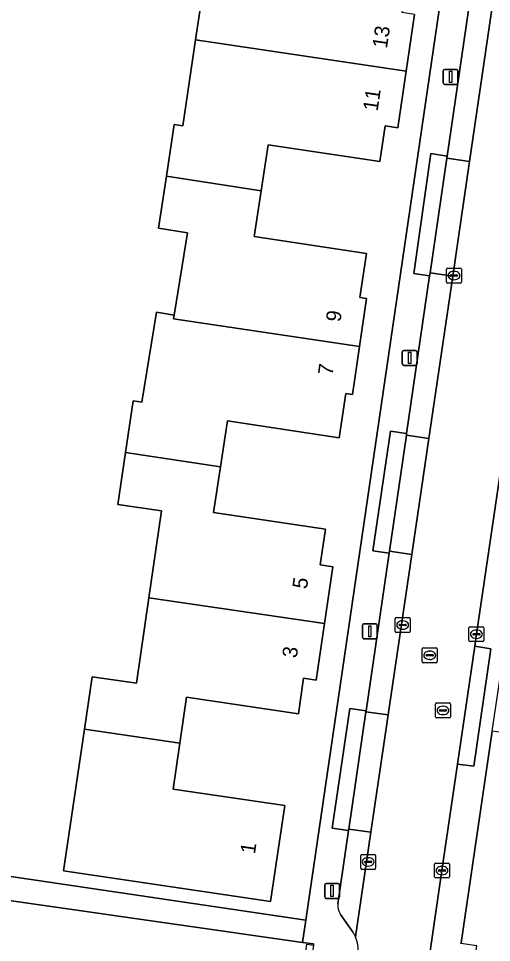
# Model space of a CAD drawing. Extents: x 164148 to 165261, y 382513 to 383432.
# Drawn here: x 164508.4 to 164540.2, y 382867.8 to 382929.8 of the extents above; entities that cross this region are included whole.
import ezdxf

# ---------------------------------------------------------------- set-up
doc = ezdxf.new("R2010")
doc.units = 0
for name, color, linetype in [('IMGEO_Erf', 7, 'Continuous'), ('IMGEO_Greppel_droge_sloot', 7, 'Continuous'), ('IMGEO_Groenvoorziening', 7, 'Continuous'), ('IMGEO_Kolk', 7, 'Continuous'), ('IMGEO_Lichtmast', 7, 'Continuous'), ('IMGEO_Pand', 7, 'Continuous'), ('IMGEO_Pand_nummerreeks', 7, 'Continuous'), ('IMGEO_Parkeervlak_open', 7, 'Continuous'), ('IMGEO_Rijbaan_lokaal_open', 7, 'Continuous'), ('IMGEO_Rioolput', 7, 'Continuous'), ('IMGEO_Voetpad_open', 7, 'Continuous')]:
    doc.layers.add(name, color=color, linetype=linetype)

msp = doc.modelspace()

# ---------------------------------------------------------------- linework, layer by layer
at = {"layer": 'IMGEO_Erf'}
msp.add_lwpolyline([(164536.67, 382930.425), (164544.133, 382980.726), (164542.913, 382982.243), (164519.298, 382985.737), (164495.986, 382989.176), (164494.523, 382988.072), (164478.67, 382881.048), (164478.137, 382876.668), (164527.73, 382869.322)], close=True, dxfattribs=at)
for points in [[(164535.03, 382930.101), (164534.467, 382926.303), (164533.904, 382922.504), (164533.057, 382922.633), (164532.702, 382920.244), (164525.197, 382921.358), (164524.728, 382918.276), (164524.258, 382915.194), (164531.797, 382914.074), (164531.359, 382911.106), (164531.805, 382911.044), (164531.329, 382907.829), (164530.852, 382904.613), (164530.422, 382904.67), (164529.967, 382901.7), (164522.469, 382902.828), (164522.001, 382899.752), (164521.532, 382896.676), (164529.042, 382895.565), (164528.691, 382893.168), (164529.541, 382893.043), (164528.982, 382889.238), (164528.423, 382885.433), (164527.578, 382885.569), (164527.229, 382883.186), (164519.728, 382884.295), (164519.273, 382881.212), (164518.818, 382878.129), (164526.315, 382877.031), (164525.363, 382870.591), (164511.47, 382872.646), (164512.877, 382882.156), (164513.394, 382885.655), (164516.368, 382885.227), (164517.196, 382890.97), (164518.037, 382896.807), (164515.115, 382897.228), (164515.63, 382900.722), (164516.141, 382904.189), (164516.733, 382904.093), (164517.701, 382910.122), (164518.893, 382909.931), (164519.78, 382915.457), (164517.849, 382915.767), (164518.367, 382919.245), (164518.884, 382922.722), (164519.473, 382922.626), (164520.329, 382928.398), (164521.189, 382934.198)], [(164547.639, 382932.325), (164544.836, 382913.278), (164561.257, 382910.871), (164561.444, 382912.157), (164568.951, 382911.025), (164568.121, 382905.277), (164560.589, 382906.422), (164560.768, 382907.691), (164544.373, 382910.128), (164540.7, 382885.173), (164557.112, 382882.794), (164557.31, 382884.103), (164564.82, 382882.958), (164563.954, 382877.188), (164556.429, 382878.318), (164556.635, 382879.621), (164540.236, 382882.018), (164538.147, 382867.82)]]:
    msp.add_lwpolyline(points, dxfattribs=at)
at = {"layer": 'IMGEO_Greppel_droge_sloot'}
msp.add_lwpolyline([(164527.808, 382867.71), (164528.242, 382867.643), (164528.255, 382867.732), (164527.513, 382867.841), (164483.733, 382874.094), (164468.94, 382876.903), (164467.772, 382876.998), (164467.128, 382872.489), (164466.901, 382870.898), (164466.447, 382867.72), (164465.924, 382864.054), (164484.051, 382861.245), (164524.835, 382854.782), (164525.957, 382854.773), (164526.609, 382859.328), (164526.913, 382861.453), (164527.19, 382863.393)], close=True, dxfattribs=at)
at = {"layer": 'IMGEO_Groenvoorziening'}
msp.add_lwpolyline([(164478.137, 382876.668), (164478.67, 382881.048), (164471.849, 382882.015), (164467.712, 382879.403), (164467.374, 382877.067), (164467.772, 382876.998), (164468.94, 382876.903), (164483.733, 382874.094), (164527.513, 382867.841), (164527.73, 382869.322)], close=True, dxfattribs=at)
at = {"layer": 'IMGEO_Kolk'}
for p, q in [((164537.168, 382912.156), (164537.168, 382913.008)), ((164537.243, 382913.082), (164538.095, 382913.082)), ((164538.169, 382913.008), (164538.169, 382912.156)), ((164537.427, 382912.576), (164537.427, 382912.588)), ((164537.865, 382912.539), (164537.467, 382912.539)), ((164537.47, 382912.625), (164537.868, 382912.625)), ((164537.679, 382912.302), (164537.654, 382912.302)), ((164537.656, 382912.862), (164537.681, 382912.862)), ((164537.911, 382912.588), (164537.911, 382912.576)), ((164538.095, 382912.082), (164537.243, 382912.082)), ((164533.729, 382888.709), (164533.729, 382889.561)), ((164533.804, 382889.635), (164534.656, 382889.635)), ((164534.217, 382889.415), (164534.242, 382889.415)), ((164534.73, 382889.561), (164534.73, 382888.709)), ((164533.988, 382889.129), (164533.988, 382889.141)), ((164534.426, 382889.092), (164534.028, 382889.092)), ((164534.031, 382889.178), (164534.429, 382889.178)), ((164534.24, 382888.855), (164534.215, 382888.855)), ((164534.472, 382889.141), (164534.472, 382889.129)), ((164538.68, 382888.093), (164538.68, 382888.945)), ((164538.755, 382889.019), (164539.607, 382889.019)), ((164539.168, 382888.799), (164539.193, 382888.799)), ((164539.681, 382888.945), (164539.681, 382888.093)), ((164534.656, 382888.635), (164533.804, 382888.635)), ((164538.939, 382888.513), (164538.939, 382888.525)), ((164539.377, 382888.476), (164538.979, 382888.476)), ((164538.982, 382888.562), (164539.38, 382888.562)), ((164539.191, 382888.239), (164539.166, 382888.239)), ((164539.423, 382888.525), (164539.423, 382888.513)), ((164539.607, 382888.019), (164538.755, 382888.019)), ((164531.413, 382872.815), (164531.413, 382873.667)), ((164531.488, 382873.741), (164532.34, 382873.741)), ((164531.672, 382873.235), (164531.672, 382873.247)), ((164532.11, 382873.198), (164531.712, 382873.198)), ((164531.715, 382873.284), (164532.113, 382873.284)), ((164531.901, 382873.521), (164531.926, 382873.521)), ((164532.156, 382873.247), (164532.156, 382873.235)), ((164532.414, 382873.667), (164532.414, 382872.815)), ((164532.34, 382872.741), (164531.488, 382872.741)), ((164531.924, 382872.961), (164531.899, 382872.961)), ((164536.367, 382872.237), (164536.367, 382873.089)), ((164536.442, 382873.163), (164537.294, 382873.163)), ((164536.626, 382872.657), (164536.626, 382872.669)), ((164537.064, 382872.62), (164536.666, 382872.62)), ((164536.669, 382872.706), (164537.067, 382872.706)), ((164536.855, 382872.943), (164536.88, 382872.943)), ((164537.11, 382872.669), (164537.11, 382872.657)), ((164537.368, 382873.089), (164537.368, 382872.237)), ((164537.294, 382872.163), (164536.442, 382872.163)), ((164536.878, 382872.383), (164536.853, 382872.383))]:
    msp.add_line(p, q, dxfattribs=at)
for points in [[(164537.168, 382912.156), (164537.168, 382913.008)], [(164537.243, 382913.082), (164538.095, 382913.082)], [(164538.169, 382913.008), (164538.169, 382912.156)], [(164538.095, 382912.082), (164537.243, 382912.082)], [(164533.729, 382888.709), (164533.729, 382889.561)], [(164533.804, 382889.635), (164534.656, 382889.635)], [(164534.73, 382889.561), (164534.73, 382888.709)], [(164538.68, 382888.093), (164538.68, 382888.945)], [(164538.755, 382889.019), (164539.607, 382889.019)], [(164539.681, 382888.945), (164539.681, 382888.093)], [(164534.656, 382888.635), (164533.804, 382888.635)], [(164539.607, 382888.019), (164538.755, 382888.019)], [(164531.413, 382872.815), (164531.413, 382873.667)], [(164531.488, 382873.741), (164532.34, 382873.741)], [(164532.414, 382873.667), (164532.414, 382872.815)], [(164532.34, 382872.741), (164531.488, 382872.741)], [(164536.367, 382872.237), (164536.367, 382873.089)], [(164536.442, 382873.163), (164537.294, 382873.163)], [(164537.368, 382873.089), (164537.368, 382872.237)], [(164537.294, 382872.163), (164536.442, 382872.163)]]:
    msp.add_lwpolyline(points, dxfattribs=at)
for centre, radius, start, end in [((164537.245, 382913.006), 0.0765, 91.55205, 178.44795), ((164537.245, 382913.006), 0.0765, 91.55205, 178.44795), ((164538.093, 382913.006), 0.0765, 1.55205, 88.44795), ((164538.093, 382913.006), 0.0765, 1.55205, 88.44795), ((164537.467, 382912.585), 0.0403, 85.87752, 175.75265), ((164537.464, 382912.575), 0.0366, 178.93798, 274.71019), ((164537.868, 382912.582), 0.043, 264.86636, 352.45326), ((164537.872, 382912.587), 0.0386, 1.73085, 96.63898), ((164537.245, 382912.158), 0.0765, 181.55205, 268.44795), ((164537.245, 382912.158), 0.0765, 181.55205, 268.44795), ((164538.093, 382912.158), 0.0765, 271.55205, 358.44795), ((164538.093, 382912.158), 0.0765, 271.55205, 358.44795), ((164533.806, 382889.559), 0.0765, 91.55205, 178.44795), ((164533.806, 382889.559), 0.0765, 91.55205, 178.44795), ((164534.654, 382889.559), 0.0765, 1.55205, 88.44795), ((164534.654, 382889.559), 0.0765, 1.55205, 88.44795), ((164533.806, 382888.711), 0.0765, 181.55205, 268.44795), ((164533.806, 382888.711), 0.0765, 181.55205, 268.44795), ((164534.028, 382889.138), 0.0403, 85.87752, 175.75265), ((164534.025, 382889.128), 0.0366, 178.93798, 274.71019), ((164534.429, 382889.135), 0.043, 264.86636, 352.45326), ((164534.433, 382889.14), 0.0386, 1.73085, 96.63898), ((164534.654, 382888.711), 0.0765, 271.55205, 358.44795), ((164534.654, 382888.711), 0.0765, 271.55205, 358.44795), ((164538.757, 382888.943), 0.0765, 91.55205, 178.44795), ((164538.757, 382888.943), 0.0765, 91.55205, 178.44795), ((164539.605, 382888.943), 0.0765, 1.55205, 88.44795), ((164539.605, 382888.943), 0.0765, 1.55205, 88.44795), ((164538.757, 382888.095), 0.0765, 181.55205, 268.44795), ((164538.757, 382888.095), 0.0765, 181.55205, 268.44795), ((164538.979, 382888.522), 0.0403, 85.87752, 175.75265), ((164538.976, 382888.512), 0.0366, 178.93798, 274.71019), ((164539.38, 382888.519), 0.043, 264.86636, 352.45326), ((164539.384, 382888.524), 0.0386, 1.73085, 96.63898), ((164539.605, 382888.095), 0.0765, 271.55205, 358.44795), ((164539.605, 382888.095), 0.0765, 271.55205, 358.44795), ((164531.49, 382873.665), 0.0765, 91.55205, 178.44795), ((164531.49, 382873.665), 0.0765, 91.55205, 178.44795), ((164531.712, 382873.244), 0.0403, 85.87752, 175.75265), ((164531.709, 382873.234), 0.0366, 178.93798, 274.71019), ((164532.113, 382873.241), 0.043, 264.86636, 352.45326), ((164532.117, 382873.246), 0.0386, 1.73085, 96.63898), ((164532.338, 382873.665), 0.0765, 1.55205, 88.44795), ((164532.338, 382873.665), 0.0765, 1.55205, 88.44795), ((164531.49, 382872.817), 0.0765, 181.55205, 268.44795), ((164531.49, 382872.817), 0.0765, 181.55205, 268.44795), ((164532.338, 382872.817), 0.0765, 271.55205, 358.44795), ((164532.338, 382872.817), 0.0765, 271.55205, 358.44795), ((164536.444, 382873.087), 0.0765, 91.55205, 178.44795), ((164536.444, 382873.087), 0.0765, 91.55205, 178.44795), ((164536.666, 382872.666), 0.0403, 85.87752, 175.75265), ((164536.663, 382872.656), 0.0366, 178.93798, 274.71019), ((164537.067, 382872.663), 0.043, 264.86636, 352.45326), ((164537.071, 382872.668), 0.0386, 1.73085, 96.63898), ((164537.292, 382873.087), 0.0765, 1.55205, 88.44795), ((164537.292, 382873.087), 0.0765, 1.55205, 88.44795), ((164536.444, 382872.239), 0.0765, 181.55205, 268.44795), ((164536.444, 382872.239), 0.0765, 181.55205, 268.44795), ((164537.292, 382872.239), 0.0765, 271.55205, 358.44795), ((164537.292, 382872.239), 0.0765, 271.55205, 358.44795)]:
    msp.add_arc(centre, radius, start, end, dxfattribs=at)
for centre, major_axis, ratio, start_param, end_param in [((164537.655, 382912.582), (-0.387, 0.002), 0.722429, 4.712389, 7.853982), ((164537.68, 382912.582), (-0.39, 0.002), 0.717154, 1.570796, 4.712389), ((164534.216, 382889.135), (-0.387, 0.002), 0.722429, 4.712389, 7.853982), ((164534.241, 382889.135), (-0.39, 0.002), 0.717154, 1.570796, 4.712389), ((164539.167, 382888.519), (-0.387, 0.002), 0.722429, 4.712389, 7.853982), ((164539.192, 382888.519), (-0.39, 0.002), 0.717154, 1.570796, 4.712389), ((164531.9, 382873.241), (-0.387, 0.002), 0.722429, 4.712389, 7.853982), ((164531.925, 382873.241), (-0.39, 0.002), 0.717154, 1.570796, 4.712389), ((164536.854, 382872.663), (-0.387, 0.002), 0.722429, 4.712389, 7.853982), ((164536.879, 382872.663), (-0.39, 0.002), 0.717154, 1.570796, 4.712389)]:
    msp.add_ellipse(centre, major_axis=major_axis, ratio=ratio, start_param=start_param, end_param=end_param, dxfattribs=at)
at = {"layer": 'IMGEO_Lichtmast'}
for p, q in [((164536.949, 382925.514), (164536.949, 382926.314)), ((164536.949, 382926.314), (164536.949, 382925.514)), ((164537.049, 382926.414), (164537.839, 382926.414)), ((164537.839, 382926.414), (164537.049, 382926.414)), ((164537.939, 382926.314), (164537.939, 382925.514)), ((164537.939, 382925.514), (164537.939, 382926.314)), ((164537.839, 382925.414), (164537.049, 382925.414)), ((164537.049, 382925.414), (164537.839, 382925.414)), ((164534.204, 382906.658), (164534.204, 382907.458)), ((164534.204, 382907.458), (164534.204, 382906.658)), ((164534.304, 382907.558), (164535.094, 382907.558)), ((164535.094, 382907.558), (164534.304, 382907.558)), ((164535.194, 382907.458), (164535.194, 382906.658)), ((164535.194, 382906.658), (164535.194, 382907.458)), ((164535.094, 382906.558), (164534.304, 382906.558)), ((164534.304, 382906.558), (164535.094, 382906.558)), ((164531.531, 382888.315), (164531.531, 382889.115)), ((164531.531, 382889.115), (164531.531, 382888.315)), ((164531.631, 382889.215), (164532.421, 382889.215)), ((164532.421, 382889.215), (164531.631, 382889.215)), ((164532.521, 382889.115), (164532.521, 382888.315)), ((164532.521, 382888.315), (164532.521, 382889.115)), ((164532.421, 382888.215), (164531.631, 382888.215)), ((164531.631, 382888.215), (164532.421, 382888.215)), ((164528.999, 382870.893), (164528.999, 382871.693)), ((164528.999, 382871.693), (164528.999, 382870.893)), ((164529.099, 382871.793), (164529.889, 382871.793)), ((164529.889, 382871.793), (164529.099, 382871.793)), ((164529.989, 382871.693), (164529.989, 382870.893)), ((164529.989, 382870.893), (164529.989, 382871.693)), ((164529.889, 382870.793), (164529.099, 382870.793)), ((164529.099, 382870.793), (164529.889, 382870.793))]:
    msp.add_line(p, q, dxfattribs=at)
for points in [[(164537.369, 382926.289), (164537.519, 382926.289), (164537.519, 382925.539), (164537.369, 382925.539), (164537.369, 382926.289)], [(164534.624, 382907.433), (164534.774, 382907.433), (164534.774, 382906.683), (164534.624, 382906.683), (164534.624, 382907.433)], [(164531.951, 382889.09), (164532.101, 382889.09), (164532.101, 382888.34), (164531.951, 382888.34), (164531.951, 382889.09)], [(164529.419, 382871.668), (164529.569, 382871.668), (164529.569, 382870.918), (164529.419, 382870.918), (164529.419, 382871.668)]]:
    msp.add_lwpolyline(points, dxfattribs=at)
for centre, start, end in [((164537.049, 382926.314), 90, 180), ((164537.049, 382926.314), 90, 180), ((164537.839, 382926.314), 0, 90), ((164537.839, 382926.314), 360, 90), ((164537.049, 382925.514), 180, 270), ((164537.049, 382925.514), 180, 270), ((164537.839, 382925.514), 270, 0), ((164537.839, 382925.514), 270, 0), ((164534.304, 382907.458), 90, 180), ((164534.304, 382907.458), 90, 180), ((164535.094, 382907.458), 0, 90), ((164535.094, 382907.458), 360, 90), ((164534.304, 382906.658), 180, 270), ((164534.304, 382906.658), 180, 270), ((164535.094, 382906.658), 270, 0), ((164535.094, 382906.658), 270, 0), ((164531.631, 382889.115), 90, 180), ((164531.631, 382889.115), 90, 180), ((164532.421, 382889.115), 0, 90), ((164532.421, 382889.115), 360, 90), ((164531.631, 382888.315), 180, 270), ((164531.631, 382888.315), 180, 270), ((164532.421, 382888.315), 270, 0), ((164532.421, 382888.315), 270, 0), ((164529.099, 382871.693), 90, 180), ((164529.099, 382871.693), 90, 180), ((164529.889, 382871.693), 0, 90), ((164529.889, 382871.693), 360, 90), ((164529.099, 382870.893), 180, 270), ((164529.099, 382870.893), 180, 270), ((164529.889, 382870.893), 270, 0), ((164529.889, 382870.893), 270, 0)]:
    msp.add_arc(centre, 0.1, start, end, dxfattribs=at)
at = {"layer": 'IMGEO_Pand'}
for points in [[(164534.539, 382932.609), (164527.04, 382933.727), (164527.481, 382936.808), (164521.094, 382937.721), (164520.588, 382934.288), (164521.189, 382934.198), (164520.329, 382928.398), (164534.467, 382926.303), (164535.03, 382930.101), (164534.185, 382930.228)], [(164534.467, 382926.303), (164520.329, 382928.398), (164519.473, 382922.626), (164518.884, 382922.722), (164518.367, 382919.245), (164524.728, 382918.276), (164525.197, 382921.358), (164532.702, 382920.244), (164533.057, 382922.633), (164533.904, 382922.504)], [(164531.797, 382914.074), (164524.258, 382915.194), (164524.728, 382918.276), (164518.367, 382919.245), (164517.849, 382915.767), (164519.78, 382915.457), (164518.893, 382909.931), (164518.852, 382909.677), (164531.329, 382907.829), (164531.805, 382911.044), (164531.359, 382911.106)], [(164531.329, 382907.829), (164518.852, 382909.677), (164518.893, 382909.931), (164517.701, 382910.122), (164516.733, 382904.093), (164516.141, 382904.189), (164515.63, 382900.722), (164522.001, 382899.752), (164522.469, 382902.828), (164529.967, 382901.7), (164530.422, 382904.67), (164530.852, 382904.613)], [(164529.042, 382895.565), (164521.532, 382896.676), (164522.001, 382899.752), (164515.63, 382900.722), (164515.115, 382897.228), (164518.037, 382896.807), (164517.196, 382890.97), (164528.982, 382889.238), (164529.541, 382893.043), (164528.691, 382893.168)], [(164528.982, 382889.238), (164517.196, 382890.97), (164516.368, 382885.227), (164513.394, 382885.655), (164512.877, 382882.156), (164519.273, 382881.212), (164519.728, 382884.295), (164527.229, 382883.186), (164527.578, 382885.569), (164528.423, 382885.433)], [(164526.315, 382877.031), (164518.818, 382878.129), (164519.273, 382881.212), (164512.877, 382882.156), (164511.47, 382872.646), (164525.363, 382870.591)]]:
    msp.add_lwpolyline(points, close=True, dxfattribs=at)
at = {"layer": 'IMGEO_Parkeervlak_open'}
for points in [[(164540.312, 382931.053), (164538.776, 382931.269), (164538.763, 382931.18), (164537.216, 382920.605), (164537.196, 382920.467), (164538.721, 382920.241)], [(164537.586, 382912.536), (164536.069, 382912.76), (164536.041, 382912.575), (164534.494, 382901.996), (164534.476, 382901.877), (164535.985, 382901.658)], [(164534.839, 382893.869), (164533.337, 382894.09), (164533.317, 382893.95), (164531.771, 382883.381), (164531.762, 382883.32), (164533.255, 382883.11)]]:
    msp.add_lwpolyline(points, close=True, dxfattribs=at)
for points in [[(164532.094, 382875.226), (164530.609, 382875.44), (164530.594, 382875.339), (164529.877, 382870.437)], [(164531.063, 382868.222), (164532.094, 382875.226)], [(164530.061, 382869.713), (164530.863, 382868.563)]]:
    msp.add_lwpolyline(points, dxfattribs=at)
for centre, radius, start, end in [((164531.014, 382870.341), 1.141, 175.14797, 213.37097), ((164529.289, 382867.411), 1.951, 24.57653, 36.20759)]:
    msp.add_arc(centre, radius, start, end, dxfattribs=at)
at = {"layer": 'IMGEO_Rijbaan_lokaal_open'}
for points in [[(164539.063, 382887.71), (164539.181, 382888.519), (164542.028, 382907.811), (164542.057, 382908.011), (164543.215, 382915.889), (164545.41, 382930.835), (164546.177, 382936.01), (164547.348, 382943.904), (164548.568, 382952.133), (164550.358, 382964.172), (164551.53, 382972.055), (164553.09, 382982.535)], [(164547.198, 382977.836), (164545.744, 382967.958), (164544.187, 382957.375), (164543.057, 382949.701), (164541.441, 382938.72), (164540.312, 382931.053), (164538.721, 382920.241), (164537.586, 382912.536), (164535.985, 382901.658), (164534.839, 382893.869), (164533.255, 382883.11), (164532.094, 382875.226), (164531.063, 382868.222)], [(164534.057, 382852.71), (164536.025, 382866.945), (164536.868, 382872.663), (164537.91, 382879.804), (164539.063, 382887.71)]]:
    msp.add_lwpolyline(points, dxfattribs=at)
msp.add_arc((164529.284, 382867.405), 1.957, 350.53101, 24.67146, dxfattribs=at)
at = {"layer": 'IMGEO_Rioolput'}
for p, q in [((164535.548, 382886.677), (164535.548, 382887.529)), ((164535.623, 382887.603), (164536.475, 382887.603)), ((164536.549, 382887.529), (164536.549, 382886.677)), ((164535.807, 382887.097), (164535.807, 382887.109)), ((164536.245, 382887.06), (164535.847, 382887.06)), ((164535.85, 382887.146), (164536.248, 382887.146)), ((164536.036, 382887.383), (164536.061, 382887.383)), ((164536.291, 382887.109), (164536.291, 382887.097)), ((164536.475, 382886.603), (164535.623, 382886.603)), ((164536.059, 382886.823), (164536.034, 382886.823)), ((164536.435, 382882.979), (164536.435, 382883.831)), ((164536.51, 382883.905), (164537.362, 382883.905)), ((164537.436, 382883.831), (164537.436, 382882.979)), ((164536.694, 382883.399), (164536.694, 382883.411)), ((164537.132, 382883.362), (164536.734, 382883.362)), ((164536.737, 382883.448), (164537.135, 382883.448)), ((164536.946, 382883.125), (164536.921, 382883.125)), ((164536.923, 382883.685), (164536.948, 382883.685)), ((164537.178, 382883.411), (164537.178, 382883.399)), ((164537.362, 382882.905), (164536.51, 382882.905))]:
    msp.add_line(p, q, dxfattribs=at)
for points in [[(164535.548, 382886.677), (164535.548, 382887.529)], [(164535.623, 382887.603), (164536.475, 382887.603)], [(164536.549, 382887.529), (164536.549, 382886.677)], [(164536.475, 382886.603), (164535.623, 382886.603)], [(164536.435, 382882.979), (164536.435, 382883.831)], [(164536.51, 382883.905), (164537.362, 382883.905)], [(164537.436, 382883.831), (164537.436, 382882.979)], [(164537.362, 382882.905), (164536.51, 382882.905)]]:
    msp.add_lwpolyline(points, dxfattribs=at)
for centre, radius, start, end in [((164535.625, 382887.527), 0.0765, 91.55205, 178.44795), ((164535.625, 382887.527), 0.0765, 91.55205, 178.44795), ((164536.473, 382887.527), 0.0765, 1.55205, 88.44795), ((164536.473, 382887.527), 0.0765, 1.55205, 88.44795), ((164535.847, 382887.106), 0.0403, 85.87752, 175.75265), ((164535.844, 382887.096), 0.0366, 178.93798, 274.71019), ((164536.248, 382887.103), 0.043, 264.86636, 352.45326), ((164536.252, 382887.108), 0.0386, 1.73085, 96.63898), ((164535.625, 382886.679), 0.0765, 181.55205, 268.44795), ((164535.625, 382886.679), 0.0765, 181.55205, 268.44795), ((164536.473, 382886.679), 0.0765, 271.55205, 358.44795), ((164536.473, 382886.679), 0.0765, 271.55205, 358.44795), ((164536.512, 382883.829), 0.0765, 91.55205, 178.44795), ((164536.512, 382883.829), 0.0765, 91.55205, 178.44795), ((164537.36, 382883.829), 0.0765, 1.55205, 88.44795), ((164537.36, 382883.829), 0.0765, 1.55205, 88.44795), ((164536.734, 382883.408), 0.0403, 85.87752, 175.75265), ((164536.731, 382883.398), 0.0366, 178.93798, 274.71019), ((164537.135, 382883.405), 0.043, 264.86636, 352.45326), ((164537.139, 382883.41), 0.0386, 1.73085, 96.63898), ((164536.512, 382882.981), 0.0765, 181.55205, 268.44795), ((164536.512, 382882.981), 0.0765, 181.55205, 268.44795), ((164537.36, 382882.981), 0.0765, 271.55205, 358.44795), ((164537.36, 382882.981), 0.0765, 271.55205, 358.44795)]:
    msp.add_arc(centre, radius, start, end, dxfattribs=at)
for centre, major_axis, ratio, start_param, end_param in [((164536.035, 382887.103), (-0.387, 0.002), 0.722429, 4.712389, 7.853982), ((164536.06, 382887.103), (-0.39, 0.002), 0.717154, 1.570796, 4.712389), ((164536.922, 382883.405), (-0.387, 0.002), 0.722429, 4.712389, 7.853982), ((164536.947, 382883.405), (-0.39, 0.002), 0.717154, 1.570796, 4.712389)]:
    msp.add_ellipse(centre, major_axis=major_axis, ratio=ratio, start_param=start_param, end_param=end_param, dxfattribs=at)
at = {"layer": 'IMGEO_Voetpad_open'}
for points in [[(164496.395, 382992.705), (164495.986, 382989.176), (164519.298, 382985.737), (164542.913, 382982.243), (164544.133, 382980.726), (164536.67, 382930.425), (164527.73, 382869.322), (164527.513, 382867.841), (164528.255, 382867.732), (164528.242, 382867.643), (164527.339, 382861.387), (164526.374, 382854.707)], [(164553.09, 382982.535), (164551.53, 382972.055), (164552.628, 382971.896), (164551.443, 382964.04), (164550.358, 382964.172), (164548.568, 382952.133), (164547.348, 382943.904), (164548.444, 382943.762), (164547.265, 382935.866), (164546.177, 382936.01), (164545.41, 382930.835), (164543.215, 382915.889), (164544.281, 382915.734), (164543.135, 382907.871), (164542.057, 382908.011), (164542.028, 382907.811), (164539.181, 382888.519), (164539.063, 382887.71), (164540.151, 382887.546), (164539.003, 382879.661), (164537.91, 382879.804), (164536.868, 382872.663), (164536.025, 382866.945), (164534.057, 382852.71)], [(164529.877, 382870.437), (164530.594, 382875.339), (164529.503, 382875.504), (164530.69, 382883.53), (164531.771, 382883.381), (164533.317, 382893.95), (164532.221, 382894.112), (164533.408, 382902.146), (164534.494, 382901.996), (164536.041, 382912.575), (164534.969, 382912.724), (164536.127, 382920.767), (164537.216, 382920.605), (164538.763, 382931.18), (164537.668, 382931.349), (164538.838, 382939.231), (164539.933, 382939.066), (164541.525, 382949.778), (164540.437, 382949.95), (164541.607, 382957.827), (164542.695, 382957.645), (164544.247, 382968.083)], [(164537.064, 382852.92), (164538.061, 382859.718), (164538.958, 382865.839), (164539.217, 382867.609), (164538.138, 382867.763), (164538.147, 382867.82), (164540.236, 382882.018), (164540.7, 382885.173), (164544.373, 382910.128)], [(164530.863, 382868.563), (164530.061, 382869.713)]]:
    msp.add_lwpolyline(points, dxfattribs=at)
for points in [[(164537.196, 382920.467), (164537.216, 382920.605), (164536.127, 382920.767), (164534.969, 382912.724), (164536.041, 382912.575), (164536.069, 382912.76)], [(164538.721, 382920.241), (164537.196, 382920.467), (164536.069, 382912.76), (164537.586, 382912.536)], [(164534.476, 382901.877), (164534.494, 382901.996), (164533.408, 382902.146), (164532.221, 382894.112), (164533.317, 382893.95), (164533.337, 382894.09)], [(164535.985, 382901.658), (164534.476, 382901.877), (164533.337, 382894.09), (164534.839, 382893.869)], [(164539.063, 382887.71), (164537.91, 382879.804), (164539.003, 382879.661), (164540.151, 382887.546)], [(164531.762, 382883.32), (164531.771, 382883.381), (164530.69, 382883.53), (164529.503, 382875.504), (164530.594, 382875.339), (164530.609, 382875.44)], [(164533.255, 382883.11), (164531.762, 382883.32), (164530.609, 382875.44), (164532.094, 382875.226)]]:
    msp.add_lwpolyline(points, close=True, dxfattribs=at)
for centre, radius, start, end in [((164531.014, 382870.341), 1.141, 175.14797, 213.37097), ((164529.289, 382867.411), 1.951, 24.57653, 36.20759), ((164529.284, 382867.405), 1.957, 350.53101, 24.67146)]:
    msp.add_arc(centre, radius, start, end, dxfattribs=at)

# ---------------------------------------------------------------- texts
at = {"layer": 'IMGEO_Pand_nummerreeks'}
for s, rotation, p in [('13', 81.572, (164533.171, 382927.791)), ('11', 81.572, (164532.546, 382923.575)), ('9', 81.572, (164530.05, 382909.431)), ('7', 81.572, (164529.519, 382905.849)), ('5', 81.64076, (164527.8, 382891.516)), ('3', 81.64076, (164527.119, 382886.881)), ('1', 81.58919, (164524.311, 382873.73))]:
    msp.add_text(s, height=1, rotation=rotation, dxfattribs=at).set_placement(p)

doc.saveas('drawing.dxf')
